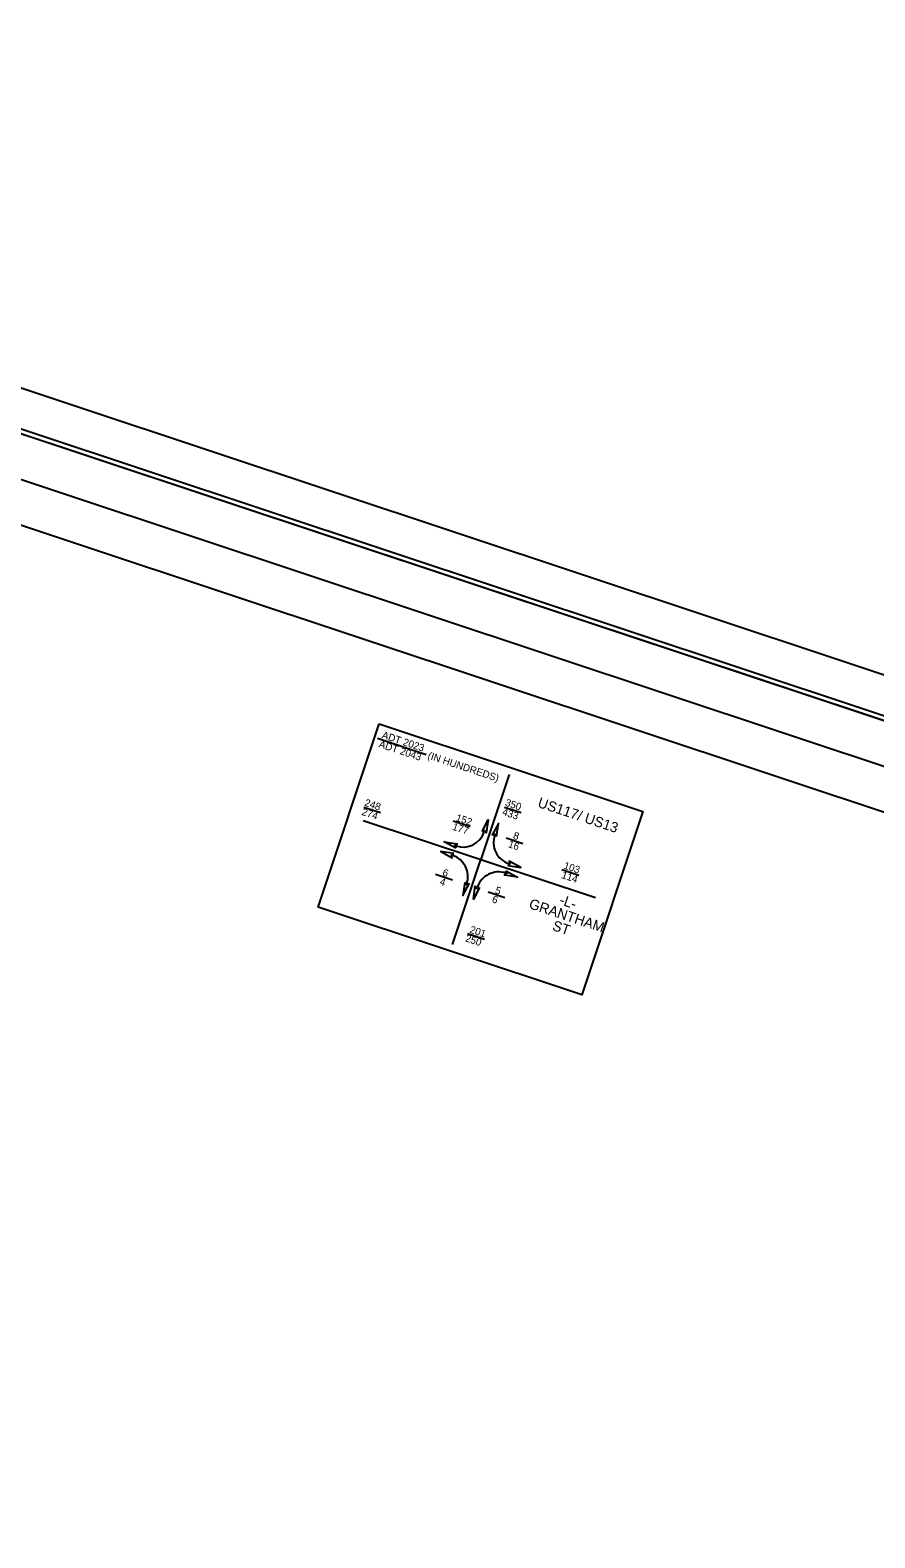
# Model space of a CAD drawing. Extents: x 2296288 to 2297455, y 600637 to 601606.
# Drawn here: x 2296872 to 2297163, y 601085 to 601606 of the extents above; entities that cross this region are included whole.
import ezdxf

# ---------------------------------------------------------------- set-up
doc = ezdxf.new("R2010")
doc.units = 0
for name, color, linetype in [('Default', 7, 'Continuous'), ('Exist DTM Drainline Cogo Comment', 7, 'Continuous'), ('Exist DTM Drainline Cogo Point CELL', 7, 'Continuous'), ('Exist Property Iron Pin Cogo Number', 7, 'Continuous'), ('Exist Roads Curbs Cogo Elevation', 7, 'Continuous'), ('Exist Roads Curbs Cogo Number', 7, 'Continuous'), ('Exist Roads Curbs Cogo Point CELL', 7, 'Continuous'), ('Exist Roads EOP Cogo Comment', 7, 'Continuous')]:
    doc.layers.add(name, color=color, linetype=linetype)

msp = doc.modelspace()

# ---------------------------------------------------------------- linework, layer by layer
at = {"layer": 'Default'}
for points in [[(2297027.59, 601328.96), (2297029.71, 601333), (2297029.06, 601328.47), (2297028.47, 601329.27)], [(2297032.6, 601327.3), (2297033.32, 601331.8), (2297031.12, 601327.79), (2297032.08, 601328.07)], [(2297017.81, 601321.36), (2297013.3, 601322.08), (2297017.32, 601319.88), (2297017.03, 601320.84)], [(2297018.5, 601323.25), (2297014.46, 601325.37), (2297018.99, 601324.72), (2297018.19, 601324.13)], [(2297035.82, 601315.37), (2297039.86, 601313.25), (2297035.33, 601313.89), (2297036.13, 601314.49)], [(2297036.45, 601317.28), (2297040.96, 601316.56), (2297036.94, 601318.75), (2297037.23, 601317.8)], [(2297021.66, 601311.34), (2297020.94, 601306.83), (2297023.14, 601310.85), (2297022.18, 601310.56)], [(2297026.73, 601309.65), (2297024.61, 601305.61), (2297025.26, 601310.14), (2297025.85, 601309.34)]]:
    msp.add_lwpolyline(points, close=True, dxfattribs=at)
for centre, start, end in [((2297021.03, 601331.29), 251.6083, 341.6083), ((2297039.24, 601325.23), 161.6082, 251.6082), ((2297015.02, 601313.4), 341.6082, 71.6082), ((2297033.29, 601307.33), 71.6083, 161.6083)]:
    msp.add_arc(centre, 7.69, start, end, dxfattribs=at)
at = {"layer": 'Exist DTM Drainline Cogo Comment'}
msp.add_lwpolyline([(2297440.6, 601276.06), (2296586.57, 601560.02), (2296387.8, 600962.2), (2297241.83, 600678.24)], close=True, dxfattribs=at)
at = {"layer": 'Exist DTM Drainline Cogo Point CELL'}
msp.add_lwpolyline([(2297421.64, 601266.56), (2296596.08, 601541.06), (2296406.77, 600971.7), (2297232.33, 600697.21)], close=True, dxfattribs=at)
at = {"layer": 'Exist Property Iron Pin Cogo Number'}
msp.add_lwpolyline([(2296425.75, 600981.21), (2297152.11, 600739.71), (2297168.67, 600769.15), (2297226.75, 600750.14), (2297369.4, 601166.29), (2297286.75, 601193.77), (2297317.24, 601285.47), (2296605.59, 601522.09)], close=True, dxfattribs=at)
at = {"layer": 'Exist Roads Curbs Cogo Elevation'}
msp.add_lwpolyline([(2296586.57, 601560.02), (2296387.82, 600962.21), (2297241.85, 600678.25), (2297402.77, 601162.3), (2297288.88, 601200.18), (2297326.7, 601313.93)], close=True, dxfattribs=at)
at = {"layer": 'Exist Roads Curbs Cogo Number'}
msp.add_lwpolyline([(2297455.02, 601287.08), (2296496.23, 601605.87), (2296287.99, 600979.58), (2297246.78, 600660.79)], close=True, dxfattribs=at)
at = {"layer": 'Exist Roads Curbs Cogo Point CELL'}
msp.add_lwpolyline([(2297448.2, 601275.15), (2296499.38, 601590.63), (2296299.64, 600989.9), (2297248.47, 600674.42)], close=True, dxfattribs=at)
at = {"layer": 'Exist Roads EOP Cogo Comment'}
for p, q in [((2296991.45, 601361.26), (2297008.33, 601355.64)), ((2297036.91, 601348.64), (2297027.16, 601319.31)), ((2296986.74, 601337.43), (2296992.56, 601335.5)), ((2297035.29, 601337.44), (2297041.1, 601335.51)), ((2296986.52, 601332.82), (2297066.78, 601306.13)), ((2297017.66, 601332.65), (2297023.47, 601330.71)), ((2297035.88, 601326.77), (2297041.69, 601324.84)), ((2297017.41, 601289.97), (2297027.16, 601319.31)), ((2297055.19, 601315.8), (2297061, 601313.86)), ((2297011.54, 601314.24), (2297017.35, 601312.31)), ((2297029.68, 601308.11), (2297035.49, 601306.18)), ((2297022.6, 601293.73), (2297028.41, 601291.8))]:
    msp.add_line(p, q, dxfattribs=at)
msp.add_lwpolyline([(2296992.08, 601366.19), (2297083.16, 601335.91), (2297062.09, 601272.56), (2296971.02, 601302.84)], close=True, dxfattribs=at)

# ---------------------------------------------------------------- texts
for s, height, p in [('ADT 2023', 2.52, (2296992.77, 601361.3)), ('ADT 2043', 2.52, (2296991.73, 601358.17)), ('(IN HUNDREDS)', 2.52, (2297008.61, 601354.22)), ('274', 2.52, (2296985.8, 601334.78)), ('248', 2.52, (2296986.78, 601337.94)), ('433', 2.52, (2297034.35, 601334.79)), ('350', 2.52, (2297035.34, 601337.95)), ('US117/ US13', 3.528, (2297046.53, 601337.53)), ('177', 2.52, (2297017.12, 601329.65)), ('152', 2.52, (2297018.34, 601332.73)), ('16', 2.52, (2297036.41, 601323.63)), ('8', 2.52, (2297038.1, 601326.55)), ('6', 2.52, (2297013.71, 601313.83)), ('114', 2.52, (2297054.82, 601312.96)), ('103', 2.52, (2297055.56, 601316.19)), ('4', 2.52, (2297012.72, 601310.68)), ('5', 2.52, (2297031.88, 601307.68)), ('6', 2.52, (2297030.8, 601304.56)), ('GRANTHAM', 3.528, (2297043.51, 601302.56)), ('-L-', 3.528, (2297054.04, 601303.93)), ('201', 2.52, (2297023.11, 601294.08)), (' ST', 3.528, (2297050.35, 601295.41)), ('250', 2.52, (2297021.59, 601291.1))]:
    msp.add_text(s, height=height, rotation=341.6082, dxfattribs=at).set_placement(p)

doc.saveas('drawing.dxf')
